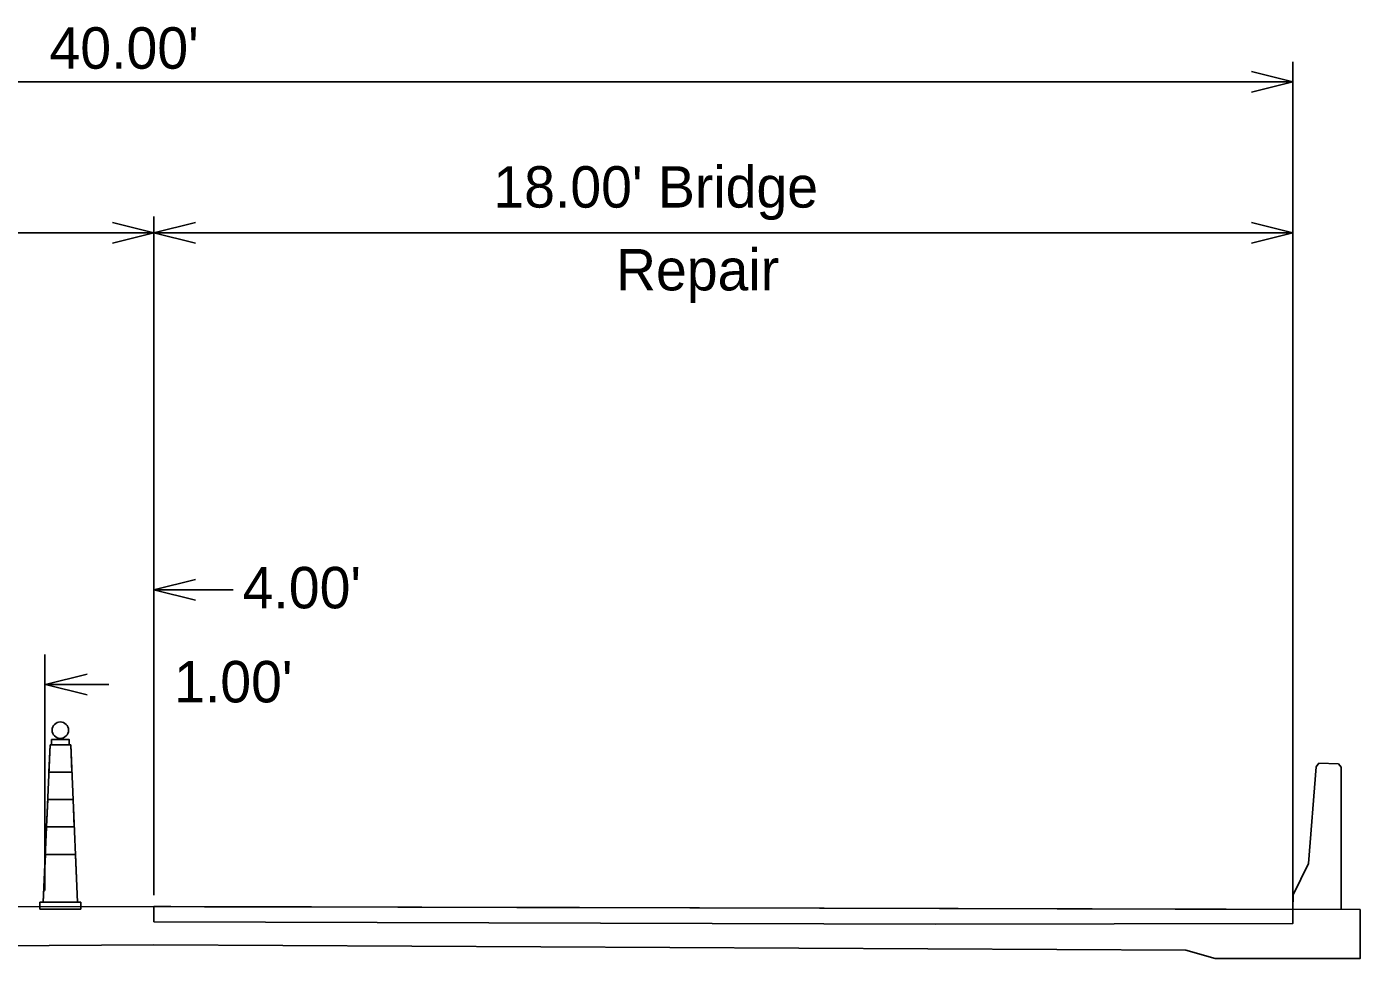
# Model space of a CAD drawing. Extents: x 8410 to 81668, y 7924 to 12712.
# Drawn here: x 15179 to 15910, y 12201 to 12712 of the extents above; entities that cross this region are included whole.
import ezdxf

# ---------------------------------------------------------------- set-up
doc = ezdxf.new("R2010")
doc.units = 0
for name, color, linetype in [('dsnCellElements', 7, 'Continuous'), ('Level 2', 7, 'Continuous'), ('Level 3', 7, 'Continuous')]:
    doc.layers.add(name, color=color, linetype=linetype)

msp = doc.modelspace()

# ---------------------------------------------------------------- linework, layer by layer
at = {"layer": 'dsnCellElements'}
for p, q in [((15192.21, 12318.19), (15188.46, 12231.94)), ((15192.21, 12318.19), (15191.56, 12303.19)), ((15203.46, 12318.19), (15192.21, 12318.19)), ((15203.46, 12318.19), (15192.21, 12318.19)), ((15207.21, 12231.94), (15203.46, 12318.19)), ((15204.11, 12303.19), (15203.46, 12318.19)), ((15204.11, 12303.19), (15191.56, 12303.19)), ((15191.56, 12303.19), (15204.11, 12303.19)), ((15190.91, 12288.19), (15190.25, 12273.19)), ((15204.77, 12288.19), (15190.91, 12288.19)), ((15204.77, 12288.19), (15190.91, 12288.19)), ((15205.42, 12273.19), (15204.77, 12288.19)), ((15205.42, 12273.19), (15190.25, 12273.19)), ((15190.25, 12273.19), (15205.42, 12273.19)), ((15189.6, 12258.19), (15188.46, 12231.94)), ((15206.07, 12258.19), (15189.6, 12258.19)), ((15206.07, 12258.19), (15189.6, 12258.19)), ((15207.21, 12231.94), (15206.07, 12258.19)), ((15209.09, 12231.94), (15186.59, 12231.94)), ((15186.59, 12231.94), (15186.59, 12228.19)), ((15188.46, 12231.94), (15207.21, 12231.94)), ((15209.09, 12228.19), (15209.09, 12231.94)), ((15209.09, 12228.19), (15186.59, 12228.19))]:
    msp.add_line(p, q, dxfattribs=at)
msp.add_lwpolyline([(15192.96, 12321.19), (15202.56, 12321.19), (15202.56, 12318.19), (15192.96, 12318.19)], close=True, dxfattribs=at)
msp.add_circle((15197.76, 12326.29), 4.5, dxfattribs=at)
at = {"layer": 'Level 2'}
for p, q in [((15873.4, 12227.99), (15873.4, 12692.79)), ((14624.81, 12681.86), (15873.4, 12681.86)), ((15249.1, 12235.78), (15249.1, 12608.13)), ((14624.81, 12599.15), (15249.1, 12599.15)), ((15249.1, 12599.15), (15873.4, 12599.15)), ((15249.1, 12403.33), (15292.55, 12403.33)), ((15189.29, 12238.33), (15189.29, 12367.75)), ((15224.4, 12351.3), (15189.71, 12351.3)), ((15886.16, 12306.27), (15881.99, 12253.24)), ((15887.55, 12308.11), (15886.16, 12306.27)), ((15898.39, 12307.86), (15887.55, 12308.11)), ((15899.74, 12305.96), (15898.39, 12307.86)), ((15899.74, 12227.92), (15899.74, 12305.96)), ((15881.99, 12253.24), (15873.48, 12235.93)), ((15873.48, 12235.93), (15873.4, 12227.99)), ((14683.59, 12205.59), (15249.1, 12208.51)), ((15814.62, 12205.59), (15249.1, 12208.51)), ((15830.84, 12201.15), (15814.62, 12205.59))]:
    msp.add_line(p, q, dxfattribs=at)
for points in [[(15850.69, 12687.54), (15873.4, 12681.86), (15850.69, 12676.19)], [(15226.4, 12604.83), (15249.1, 12599.15), (15226.4, 12593.47)], [(15271.81, 12593.47), (15249.1, 12599.15), (15271.81, 12604.83)], [(15850.69, 12604.83), (15873.4, 12599.15), (15850.69, 12593.47)], [(15271.81, 12397.65), (15249.1, 12403.33), (15271.81, 12409)], [(15212.42, 12345.62), (15189.71, 12351.3), (15212.42, 12356.97)], [(15910.32, 12227.89), (15910.32, 12201.15), (15830.84, 12201.15)]]:
    msp.add_lwpolyline(points, dxfattribs=at)
at = {"layer": 'Level 3'}
for p, q in [((15249.1, 12229.61), (14587.89, 12227.89)), ((15249.1, 12229.61), (15910.32, 12227.89)), ((15249.1, 12221.19), (15249.1, 12225.8)), ((15677.42, 12219.9), (15249.1, 12221.19))]:
    msp.add_line(p, q, dxfattribs=at)
for points in [[(15249.1, 12225.8), (15249.1, 12229.61), (15258.27, 12229.54), (15276.79, 12229.49), (15302.79, 12229.43), (15335.53, 12229.35), (15382.7, 12229.23), (15447.95, 12229.07), (15482.4, 12228.99), (15679.59, 12228.51)], [(15679.59, 12228.51), (15873.4, 12227.99), (15873.36, 12220.3), (15677.42, 12219.9)]]:
    msp.add_lwpolyline(points, dxfattribs=at)

# ---------------------------------------------------------------- texts
at = {"layer": 'Level 2'}
for s, height, p in [("40.00'", 22.709, (15191.84, 12689.12)), ("18.00' Bridge", 22.7091, (15435.11, 12612.92)), ('Repair', 22.709, (15502.34, 12567.5)), ("4.00'", 22.709, (15297.7, 12393.14)), ("1.00'", 22.709, (15260.13, 12341.54))]:
    msp.add_text(s, height=height, dxfattribs=at).set_placement(p)

doc.saveas('drawing.dxf')
